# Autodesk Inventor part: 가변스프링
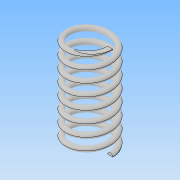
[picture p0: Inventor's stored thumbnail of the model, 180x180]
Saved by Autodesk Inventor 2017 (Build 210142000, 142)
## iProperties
Part Number: 가변스프링
Material: 일반
Document SubType Name: Modeling
Designer: user
Density: 1 g/cm^3
Appearance: 기본값
Mass: 1.24965 g
Surface Area: 25.2571 cm^2
Volume: 1.24965 cm^3
Author: user
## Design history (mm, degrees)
sketch "스케치1"
  geometry: L1 (0, 0)-(8, 0); L2 (8, 0)-(8, 37); L3 (8, 37)-(0, 37); L4 (0, 37)-(0, 0); C1 r 1 at (8, 0)
  constraints: 8 end point, 2 parallel, 1 centre point, 1 coincident, 1 horizontal, 1 perpendicular
  dimensions: "d1" = 37 distance of L2.end L1.end (derived); "d2" = 16 diameter of L2 L4; "d3" = 2 diameter of C1
feature "코일1" sketch "스케치1" pitch "d4" = 10; turns "d6" = 8; dims "d5" = 37 (= d1), "d7" = 0, angle "d8" = 90 deg, angle "d9" = 90 deg, "d10" = 0, "d11" = 0
node "작업 평면1"
sketch "스케치2"
  geometry: L1 (-9, 0)-(-7, 0) reference; L2 (-9, 0)-(-7, 0) reference; 1 further point
  constraints: 2 horizontal alignment
extrude "돌출1" cut sketch "스케치2" distance "d13" = 10; taper "d14" = 0 deg
node "작업 평면2"
sketch "스케치3"
  geometry: L1 (-7, 0)-(-9, 0) reference; 1 further point
  constraints: 1 horizontal alignment
extrude "돌출2" cut sketch "스케치3" distance "d16" = 10; taper "d17" = 0 deg
node "솔리드1"
node "절단 모서리 투영1"
node "절단 모서리 투영2"
node "절단 모서리 투영3"
other parameters: "d12" = 0, "d15" = 37 (= d1)
